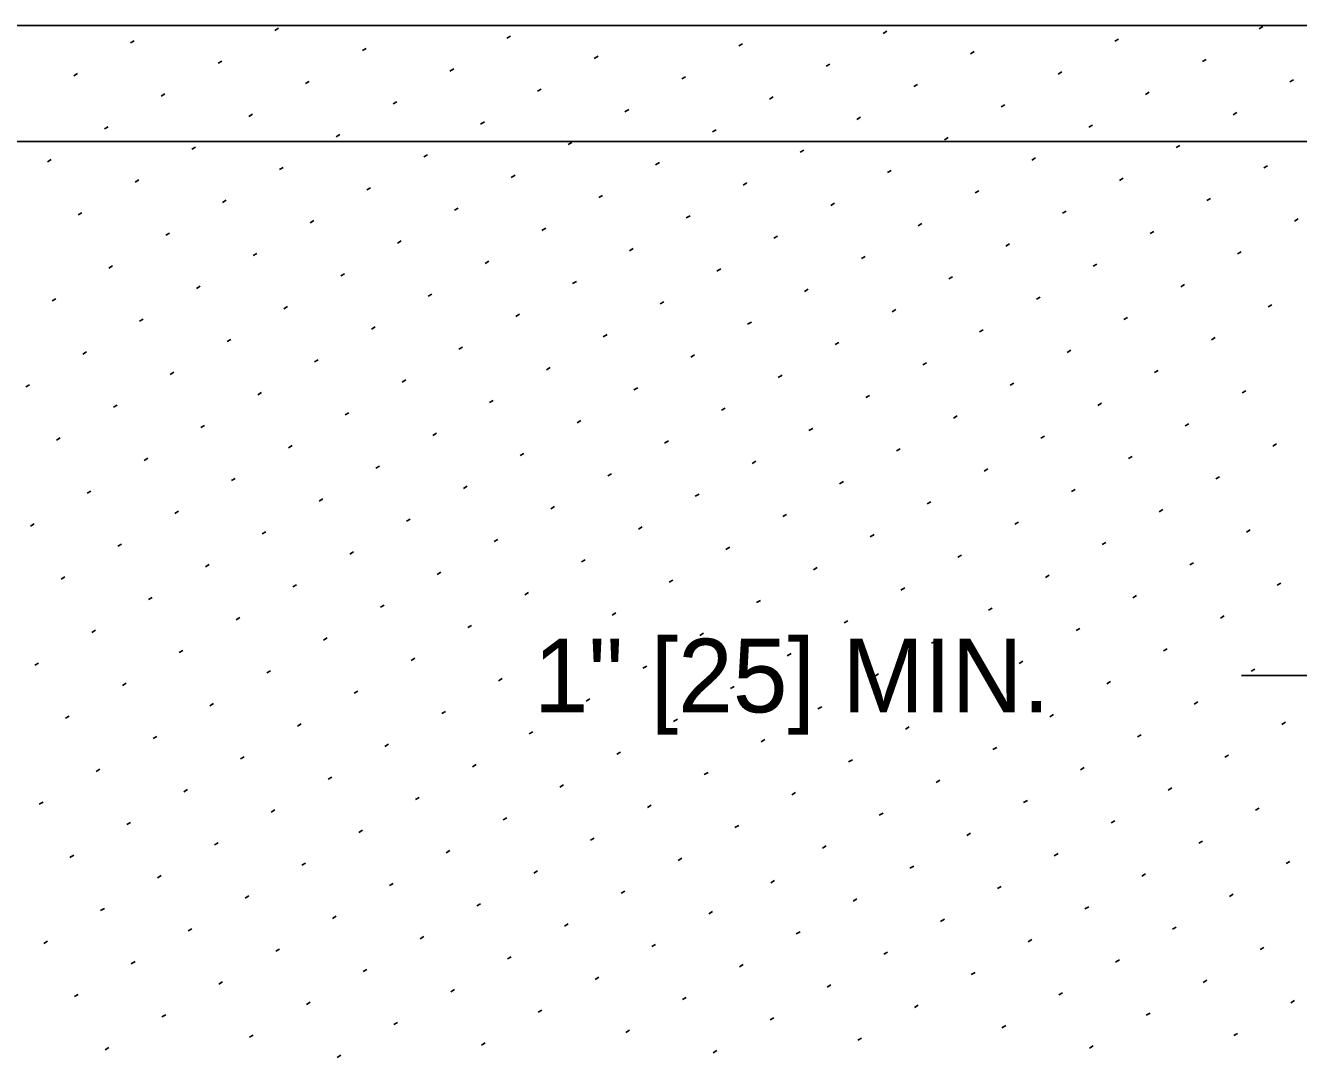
# Model space of a CAD drawing. Extents: x 49991.4 to 50021, y 49987.6 to 50011.4.
# Drawn here: x 50004.842 to 50005.88, y 49994.036 to 49994.877 of the extents above; entities that cross this region are included whole.
import ezdxf

# ---------------------------------------------------------------- set-up
doc = ezdxf.new("R2010")
doc.units = 0
for name, color, linetype in [('Level 1', 7, 'Continuous'), ('Level 2', 7, 'Continuous'), ('Level 3', 7, 'Continuous')]:
    doc.layers.add(name, color=color, linetype=linetype)

msp = doc.modelspace()

# ---------------------------------------------------------------- linework, layer by layer
at = {"layer": 'Level 1'}
for p, q in [((50004.5362, 49994.8772), (50008.0315, 49994.8772)), ((50008.0315, 49994.7828), (50001.9803, 49994.7828))]:
    msp.add_line(p, q, dxfattribs=at)
at = {"layer": 'Level 3'}
for p, q in [((50005.0452, 49994.8732), (50005.0482, 49994.875)), ((50005.3519, 49994.8771), (50005.3521, 49994.8772)), ((50005.5409, 49994.8707), (50005.5439, 49994.8725)), ((50005.8476, 49994.8746), (50005.8506, 49994.8763)), ((50004.9275, 49994.863), (50004.9305, 49994.8647)), ((50005.2342, 49994.8669), (50005.2372, 49994.8686)), ((50005.4232, 49994.8605), (50005.4262, 49994.8623)), ((50005.7299, 49994.8644), (50005.7329, 49994.8661)), ((50005.1165, 49994.8567), (50005.1195, 49994.8584)), ((50005.3055, 49994.8503), (50005.3086, 49994.8521)), ((50005.6122, 49994.8542), (50005.6152, 49994.8559)), ((50005.8012, 49994.8478), (50005.8043, 49994.8496)), ((50004.8812, 49994.8362), (50004.8842, 49994.838)), ((50004.9988, 49994.8464), (50005.0019, 49994.8482)), ((50005.1878, 49994.8401), (50005.1909, 49994.8419)), ((50005.4945, 49994.844), (50005.4976, 49994.8457)), ((50005.6836, 49994.8376), (50005.6866, 49994.8394)), ((50005.0702, 49994.8299), (50005.0732, 49994.8317)), ((50005.3769, 49994.8338), (50005.3799, 49994.8355)), ((50005.5659, 49994.8274), (50005.5689, 49994.8292)), ((50005.8726, 49994.8313), (50005.8756, 49994.833)), ((50004.9525, 49994.8197), (50004.9555, 49994.8214)), ((50005.2592, 49994.8236), (50005.2622, 49994.8253)), ((50005.4482, 49994.8172), (50005.4512, 49994.819)), ((50005.7549, 49994.8211), (50005.7579, 49994.8228)), ((50005.1415, 49994.8134), (50005.1445, 49994.8151)), ((50005.3305, 49994.807), (50005.3336, 49994.8088)), ((50005.6372, 49994.8109), (50005.6402, 49994.8126)), ((50005.0238, 49994.8031), (50005.0269, 49994.8049)), ((50005.2128, 49994.7968), (50005.2159, 49994.7986)), ((50005.5195, 49994.8007), (50005.5226, 49994.8024)), ((50005.8262, 49994.8045), (50005.8293, 49994.8063)), ((50004.9062, 49994.7929), (50004.9092, 49994.7947)), ((50005.0952, 49994.7866), (50005.0982, 49994.7883)), ((50005.4019, 49994.7905), (50005.4049, 49994.7922)), ((50005.7086, 49994.7943), (50005.7116, 49994.7961)), ((50004.9775, 49994.7764), (50004.9805, 49994.7781)), ((50005.2842, 49994.7803), (50005.2872, 49994.782)), ((50005.4732, 49994.7739), (50005.4762, 49994.7757)), ((50005.5909, 49994.7841), (50005.5939, 49994.7859)), ((50005.7799, 49994.7778), (50005.7829, 49994.7795)), ((50004.8598, 49994.7662), (50004.8628, 49994.7679)), ((50005.1665, 49994.7701), (50005.1695, 49994.7718)), ((50005.3555, 49994.7637), (50005.3586, 49994.7655)), ((50005.6622, 49994.7676), (50005.6652, 49994.7693)), ((50005.0488, 49994.7598), (50005.0519, 49994.7616)), ((50005.2378, 49994.7535), (50005.2409, 49994.7553)), ((50005.5445, 49994.7574), (50005.5476, 49994.7591)), ((50005.8512, 49994.7612), (50005.8543, 49994.763)), ((50004.9312, 49994.7496), (50004.9342, 49994.7514)), ((50005.1202, 49994.7433), (50005.1232, 49994.745)), ((50005.4269, 49994.7472), (50005.4299, 49994.7489)), ((50005.7336, 49994.751), (50005.7366, 49994.7528)), ((50005.0025, 49994.7331), (50005.0055, 49994.7348)), ((50005.3092, 49994.737), (50005.3122, 49994.7387)), ((50005.6159, 49994.7408), (50005.6189, 49994.7426)), ((50005.8049, 49994.7345), (50005.8079, 49994.7362)), ((50004.8848, 49994.7229), (50004.8878, 49994.7246)), ((50005.1915, 49994.7268), (50005.1945, 49994.7285)), ((50005.4982, 49994.7306), (50005.5012, 49994.7324)), ((50005.6872, 49994.7243), (50005.6902, 49994.726)), ((50005.0738, 49994.7165), (50005.0769, 49994.7183)), ((50005.3805, 49994.7204), (50005.3836, 49994.7222)), ((50005.5695, 49994.7141), (50005.5726, 49994.7158)), ((50005.8762, 49994.7179), (50005.8793, 49994.7197)), ((50004.9562, 49994.7063), (50004.9592, 49994.7081)), ((50005.2628, 49994.7102), (50005.2659, 49994.712)), ((50005.4519, 49994.7039), (50005.4549, 49994.7056)), ((50005.7586, 49994.7077), (50005.7616, 49994.7095)), ((50005.1452, 49994.7), (50005.1482, 49994.7017)), ((50005.3342, 49994.6937), (50005.3372, 49994.6954)), ((50005.6409, 49994.6975), (50005.6439, 49994.6993)), ((50005.8299, 49994.6912), (50005.8329, 49994.6929)), ((50005.0275, 49994.6898), (50005.0305, 49994.6915)), ((50005.2165, 49994.6834), (50005.2195, 49994.6852)), ((50005.5232, 49994.6873), (50005.5262, 49994.6891)), ((50005.7122, 49994.681), (50005.7152, 49994.6827)), ((50004.9098, 49994.6796), (50004.9128, 49994.6813)), ((50005.0988, 49994.6732), (50005.1019, 49994.675)), ((50005.4055, 49994.6771), (50005.4086, 49994.6789)), ((50005.5945, 49994.6708), (50005.5976, 49994.6725)), ((50004.9812, 49994.663), (50004.9842, 49994.6648)), ((50005.2878, 49994.6669), (50005.2909, 49994.6687)), ((50005.4769, 49994.6606), (50005.4799, 49994.6623)), ((50005.7836, 49994.6644), (50005.7866, 49994.6662)), ((50004.8635, 49994.6528), (50004.8665, 49994.6546)), ((50005.1702, 49994.6567), (50005.1732, 49994.6584)), ((50005.3592, 49994.6504), (50005.3622, 49994.6521)), ((50005.6659, 49994.6542), (50005.6689, 49994.656)), ((50005.0525, 49994.6465), (50005.0555, 49994.6482)), ((50005.2415, 49994.6401), (50005.2445, 49994.6419)), ((50005.5482, 49994.644), (50005.5512, 49994.6458)), ((50005.8549, 49994.6479), (50005.8579, 49994.6496)), ((50004.9348, 49994.6363), (50004.9378, 49994.638)), ((50005.1238, 49994.6299), (50005.1269, 49994.6317)), ((50005.4305, 49994.6338), (50005.4336, 49994.6356)), ((50005.7372, 49994.6377), (50005.7402, 49994.6394)), ((50005.0062, 49994.6197), (50005.0092, 49994.6215)), ((50005.3128, 49994.6236), (50005.3159, 49994.6254)), ((50005.6195, 49994.6275), (50005.6226, 49994.6292)), ((50005.8086, 49994.6211), (50005.8116, 49994.6229)), ((50004.8885, 49994.6095), (50004.8915, 49994.6113)), ((50005.1952, 49994.6134), (50005.1982, 49994.6151)), ((50005.5019, 49994.6173), (50005.5049, 49994.619)), ((50005.6909, 49994.6109), (50005.6939, 49994.6127)), ((50005.0775, 49994.6032), (50005.0805, 49994.6049)), ((50005.3842, 49994.6071), (50005.3872, 49994.6088)), ((50005.5732, 49994.6007), (50005.5762, 49994.6025)), ((50004.9598, 49994.593), (50004.9628, 49994.5947)), ((50005.2665, 49994.5968), (50005.2695, 49994.5986)), ((50005.4555, 49994.5905), (50005.4586, 49994.5923)), ((50005.7622, 49994.5944), (50005.7652, 49994.5961)), ((50004.8421, 49994.5828), (50004.8452, 49994.5845)), ((50005.1488, 49994.5866), (50005.1519, 49994.5884)), ((50005.3378, 49994.5803), (50005.3409, 49994.582)), ((50005.6445, 49994.5842), (50005.6476, 49994.5859)), ((50005.8336, 49994.5778), (50005.8366, 49994.5796)), ((50005.0312, 49994.5764), (50005.0342, 49994.5782)), ((50005.2202, 49994.5701), (50005.2232, 49994.5718)), ((50005.5269, 49994.574), (50005.5299, 49994.5757)), ((50005.7159, 49994.5676), (50005.7189, 49994.5694)), ((50004.9135, 49994.5662), (50004.9165, 49994.568)), ((50005.1025, 49994.5599), (50005.1055, 49994.5616)), ((50005.4092, 49994.5638), (50005.4122, 49994.5655)), ((50005.5982, 49994.5574), (50005.6012, 49994.5592)), ((50004.9848, 49994.5497), (50004.9878, 49994.5514)), ((50005.2915, 49994.5535), (50005.2945, 49994.5553)), ((50005.4805, 49994.5472), (50005.4836, 49994.549)), ((50005.7872, 49994.5511), (50005.7902, 49994.5528)), ((50004.8671, 49994.5395), (50004.8702, 49994.5412)), ((50005.1738, 49994.5433), (50005.1769, 49994.5451)), ((50005.3628, 49994.537), (50005.3659, 49994.5387)), ((50005.6695, 49994.5409), (50005.6726, 49994.5426)), ((50005.0562, 49994.5331), (50005.0592, 49994.5349)), ((50005.2452, 49994.5268), (50005.2482, 49994.5285)), ((50005.5519, 49994.5307), (50005.5549, 49994.5324)), ((50005.8586, 49994.5345), (50005.8616, 49994.5363)), ((50004.9385, 49994.5229), (50004.9415, 49994.5247)), ((50005.1275, 49994.5166), (50005.1305, 49994.5183)), ((50005.4342, 49994.5204), (50005.4372, 49994.5222)), ((50005.7409, 49994.5243), (50005.7439, 49994.5261)), ((50005.0098, 49994.5064), (50005.0128, 49994.5081)), ((50005.3165, 49994.5102), (50005.3195, 49994.512)), ((50005.6232, 49994.5141), (50005.6262, 49994.5159)), ((50005.8122, 49994.5078), (50005.8152, 49994.5095)), ((50004.8921, 49994.4962), (50004.8952, 49994.4979)), ((50005.1988, 49994.5), (50005.2019, 49994.5018)), ((50005.3878, 49994.4937), (50005.3909, 49994.4954)), ((50005.5055, 49994.5039), (50005.5086, 49994.5057)), ((50005.6945, 49994.4976), (50005.6976, 49994.4993)), ((50005.0812, 49994.4898), (50005.0842, 49994.4916)), ((50005.2702, 49994.4835), (50005.2732, 49994.4852)), ((50005.5769, 49994.4874), (50005.5799, 49994.4891)), ((50004.9635, 49994.4796), (50004.9665, 49994.4814)), ((50005.1525, 49994.4733), (50005.1555, 49994.475)), ((50005.4592, 49994.4771), (50005.4622, 49994.4789)), ((50005.7659, 49994.481), (50005.7689, 49994.4828)), ((50004.8458, 49994.4694), (50004.8488, 49994.4712)), ((50005.0348, 49994.4631), (50005.0378, 49994.4648)), ((50005.3415, 49994.4669), (50005.3445, 49994.4687)), ((50005.6482, 49994.4708), (50005.6512, 49994.4726)), ((50005.8372, 49994.4645), (50005.8402, 49994.4662)), ((50004.9171, 49994.4529), (50004.9202, 49994.4546)), ((50005.2238, 49994.4567), (50005.2269, 49994.4585)), ((50005.5305, 49994.4606), (50005.5336, 49994.4624)), ((50005.7195, 49994.4543), (50005.7226, 49994.456)), ((50005.1062, 49994.4465), (50005.1092, 49994.4483)), ((50005.4128, 49994.4504), (50005.4159, 49994.4521)), ((50005.6019, 49994.4441), (50005.6049, 49994.4458)), ((50004.9885, 49994.4363), (50004.9915, 49994.4381)), ((50005.2952, 49994.4402), (50005.2982, 49994.4419)), ((50005.4842, 49994.4338), (50005.4872, 49994.4356)), ((50005.7909, 49994.4377), (50005.7939, 49994.4395)), ((50004.8708, 49994.4261), (50004.8738, 49994.4279)), ((50005.1775, 49994.43), (50005.1805, 49994.4317)), ((50005.3665, 49994.4236), (50005.3695, 49994.4254)), ((50005.6732, 49994.4275), (50005.6762, 49994.4293)), ((50005.8622, 49994.4212), (50005.8652, 49994.4229)), ((50005.0598, 49994.4198), (50005.0628, 49994.4215)), ((50005.2488, 49994.4134), (50005.2519, 49994.4152)), ((50005.5555, 49994.4173), (50005.5586, 49994.419)), ((50005.7445, 49994.411), (50005.7476, 49994.4127)), ((50004.9421, 49994.4096), (50004.9452, 49994.4113)), ((50005.1312, 49994.4032), (50005.1342, 49994.405)), ((50005.4378, 49994.4071), (50005.4409, 49994.4088)), ((50005.6269, 49994.4008), (50005.6299, 49994.4025)), ((50005.0135, 49994.393), (50005.0165, 49994.3948)), ((50005.3202, 49994.3969), (50005.3232, 49994.3986)), ((50005.5092, 49994.3905), (50005.5122, 49994.3923)), ((50005.8159, 49994.3944), (50005.8189, 49994.3962)), ((50004.8958, 49994.3828), (50004.8988, 49994.3846)), ((50005.2025, 49994.3867), (50005.2055, 49994.3884)), ((50005.3915, 49994.3803), (50005.3945, 49994.3821)), ((50005.6982, 49994.3842), (50005.7012, 49994.386)), ((50005.0848, 49994.3765), (50005.0878, 49994.3782)), ((50005.2738, 49994.3701), (50005.2769, 49994.3719)), ((50005.5805, 49994.374), (50005.5836, 49994.3757)), ((50004.9671, 49994.3663), (50004.9702, 49994.368)), ((50005.1562, 49994.3599), (50005.1592, 49994.3617)), ((50005.4628, 49994.3638), (50005.4659, 49994.3655)), ((50005.7695, 49994.3677), (50005.7726, 49994.3694)), ((50004.8495, 49994.3561), (50004.8525, 49994.3578)), ((50005.0385, 49994.3497), (50005.0415, 49994.3515)), ((50005.3452, 49994.3536), (50005.3482, 49994.3553)), ((50005.6519, 49994.3575), (50005.6549, 49994.3592)), ((50005.8409, 49994.3511), (50005.8439, 49994.3529)), ((50004.9208, 49994.3395), (50004.9238, 49994.3413)), ((50005.2275, 49994.3434), (50005.2305, 49994.3451)), ((50005.5342, 49994.3472), (50005.5372, 49994.349)), ((50005.7232, 49994.3409), (50005.7262, 49994.3427)), ((50006.0016, 49994.3476), (50005.833, 49994.3476)), ((50005.1098, 49994.3332), (50005.1128, 49994.3349)), ((50005.4165, 49994.337), (50005.4195, 49994.3388)), ((50005.6055, 49994.3307), (50005.6086, 49994.3324)), ((50004.9921, 49994.323), (50004.9952, 49994.3247)), ((50005.2988, 49994.3268), (50005.3019, 49994.3286)), ((50005.4878, 49994.3205), (50005.4909, 49994.3222)), ((50005.7945, 49994.3244), (50005.7976, 49994.3261)), ((50004.8745, 49994.3128), (50004.8775, 49994.3145)), ((50005.1812, 49994.3166), (50005.1842, 49994.3184)), ((50005.3702, 49994.3103), (50005.3732, 49994.312)), ((50005.6769, 49994.3141), (50005.6799, 49994.3159)), ((50005.8659, 49994.3078), (50005.8689, 49994.3096)), ((50005.0635, 49994.3064), (50005.0665, 49994.3082)), ((50005.2525, 49994.3001), (50005.2555, 49994.3018)), ((50005.5592, 49994.3039), (50005.5622, 49994.3057)), ((50005.7482, 49994.2976), (50005.7512, 49994.2994)), ((50004.9458, 49994.2962), (50004.9488, 49994.298)), ((50005.1348, 49994.2899), (50005.1378, 49994.2916)), ((50005.4415, 49994.2937), (50005.4445, 49994.2955)), ((50005.6305, 49994.2874), (50005.6336, 49994.2891)), ((50005.0171, 49994.2797), (50005.0202, 49994.2814)), ((50005.3238, 49994.2835), (50005.3269, 49994.2853)), ((50005.5128, 49994.2772), (50005.5159, 49994.2789)), ((50005.8195, 49994.2811), (50005.8226, 49994.2828)), ((50004.8995, 49994.2695), (50004.9025, 49994.2712)), ((50005.2062, 49994.2733), (50005.2092, 49994.2751)), ((50005.3952, 49994.267), (50005.3982, 49994.2687)), ((50005.7019, 49994.2708), (50005.7049, 49994.2726)), ((50005.0885, 49994.2631), (50005.0915, 49994.2649)), ((50005.2775, 49994.2568), (50005.2805, 49994.2585)), ((50005.5842, 49994.2606), (50005.5872, 49994.2624)), ((50004.9708, 49994.2529), (50004.9738, 49994.2547)), ((50005.1598, 49994.2466), (50005.1628, 49994.2483)), ((50005.4665, 49994.2504), (50005.4695, 49994.2522)), ((50005.7732, 49994.2543), (50005.7762, 49994.2561)), ((50004.8531, 49994.2427), (50004.8562, 49994.2445)), ((50005.0421, 49994.2364), (50005.0452, 49994.2381)), ((50005.3488, 49994.2402), (50005.3519, 49994.242)), ((50005.6555, 49994.2441), (50005.6586, 49994.2458)), ((50005.8445, 49994.2378), (50005.8476, 49994.2395)), ((50004.9245, 49994.2262), (50004.9275, 49994.2279)), ((50005.2312, 49994.23), (50005.2342, 49994.2318)), ((50005.5378, 49994.2339), (50005.5409, 49994.2356)), ((50005.7269, 49994.2275), (50005.7299, 49994.2293)), ((50005.1135, 49994.2198), (50005.1165, 49994.2216)), ((50005.3025, 49994.2135), (50005.3055, 49994.2152)), ((50005.4202, 49994.2237), (50005.4232, 49994.2254)), ((50005.6092, 49994.2173), (50005.6122, 49994.2191)), ((50004.9958, 49994.2096), (50004.9988, 49994.2114)), ((50005.1848, 49994.2033), (50005.1878, 49994.205)), ((50005.4915, 49994.2071), (50005.4945, 49994.2089)), ((50005.7982, 49994.211), (50005.8012, 49994.2127)), ((50004.8781, 49994.1994), (50004.8812, 49994.2012)), ((50005.0671, 49994.1931), (50005.0702, 49994.1948)), ((50005.3738, 49994.1969), (50005.3769, 49994.1987)), ((50005.6805, 49994.2008), (50005.6836, 49994.2025)), ((50005.8695, 49994.1945), (50005.8726, 49994.1962)), ((50004.9495, 49994.1829), (50004.9525, 49994.1846)), ((50005.2562, 49994.1867), (50005.2592, 49994.1885)), ((50005.5628, 49994.1906), (50005.5659, 49994.1923)), ((50005.7519, 49994.1842), (50005.7549, 49994.186)), ((50005.1385, 49994.1765), (50005.1415, 49994.1783)), ((50005.4493, 49994.1788), (50005.4524, 49994.1805)), ((50005.6342, 49994.174), (50005.6372, 49994.1758)), ((50005.0208, 49994.1663), (50005.0238, 49994.1681)), ((50005.3275, 49994.1702), (50005.3305, 49994.1719)), ((50005.5165, 49994.1638), (50005.5195, 49994.1656)), ((50005.8232, 49994.1677), (50005.8262, 49994.1694)), ((50004.9031, 49994.1561), (50004.9062, 49994.1579)), ((50005.2098, 49994.16), (50005.2128, 49994.1617)), ((50005.3988, 49994.1536), (50005.4019, 49994.1554)), ((50005.7055, 49994.1575), (50005.7086, 49994.1592)), ((50005.0921, 49994.1498), (50005.0952, 49994.1515)), ((50005.2812, 49994.1434), (50005.2842, 49994.1452)), ((50005.5878, 49994.1473), (50005.5909, 49994.149)), ((50005.7769, 49994.1409), (50005.7799, 49994.1427)), ((50004.9745, 49994.1396), (50004.9775, 49994.1413)), ((50005.1635, 49994.1332), (50005.1665, 49994.135)), ((50005.4702, 49994.1371), (50005.4732, 49994.1388)), ((50005.6592, 49994.1307), (50005.6622, 49994.1325)), ((50004.8568, 49994.1294), (50004.8598, 49994.1311)), ((50005.0458, 49994.123), (50005.0488, 49994.1248)), ((50005.3525, 49994.1269), (50005.3555, 49994.1286)), ((50005.5415, 49994.1205), (50005.5445, 49994.1223)), ((50005.8482, 49994.1244), (50005.8512, 49994.1261)), ((50004.9281, 49994.1128), (50004.9312, 49994.1146)), ((50005.2348, 49994.1167), (50005.2378, 49994.1184)), ((50005.4238, 49994.1103), (50005.4269, 49994.1121)), ((50005.7305, 49994.1142), (50005.7336, 49994.1159)), ((50005.1171, 49994.1065), (50005.1202, 49994.1082)), ((50005.3062, 49994.1001), (50005.3092, 49994.1019)), ((50005.6128, 49994.104), (50005.6159, 49994.1057)), ((50004.9995, 49994.0963), (50005.0025, 49994.098)), ((50005.1885, 49994.0899), (50005.1915, 49994.0917)), ((50005.4952, 49994.0938), (50005.4982, 49994.0955)), ((50005.8019, 49994.0976), (50005.8049, 49994.0994)), ((50004.8818, 49994.0861), (50004.8848, 49994.0878)), ((50005.0708, 49994.0797), (50005.0738, 49994.0815)), ((50005.3775, 49994.0836), (50005.3805, 49994.0853)), ((50005.6842, 49994.0874), (50005.6872, 49994.0892)), ((50005.8732, 49994.0811), (50005.8762, 49994.0828)), ((50004.9531, 49994.0695), (50004.9562, 49994.0713)), ((50005.2598, 49994.0734), (50005.2628, 49994.0751)), ((50005.5665, 49994.0772), (50005.5695, 49994.079)), ((50005.7555, 49994.0709), (50005.7586, 49994.0726)), ((50005.1421, 49994.0632), (50005.1452, 49994.0649)), ((50005.4488, 49994.067), (50005.4519, 49994.0688)), ((50005.6378, 49994.0607), (50005.6409, 49994.0624)), ((50005.0245, 49994.053), (50005.0275, 49994.0547)), ((50005.3312, 49994.0568), (50005.3342, 49994.0586)), ((50005.5202, 49994.0505), (50005.5232, 49994.0522)), ((50005.8269, 49994.0543), (50005.8299, 49994.0561)), ((50004.9068, 49994.0428), (50004.9098, 49994.0445)), ((50005.2135, 49994.0466), (50005.2165, 49994.0484)), ((50005.4025, 49994.0403), (50005.4055, 49994.042)), ((50005.7092, 49994.0441), (50005.7122, 49994.0459)), ((50005.0958, 49994.0364), (50005.0988, 49994.0382))]:
    msp.add_line(p, q, dxfattribs=at)

# ---------------------------------------------------------------- texts
at = {"layer": 'Level 2'}
msp.add_text('1" [25] MIN.', height=0.06, dxfattribs=at).set_placement((50005.2561, 49994.3176))

doc.saveas('drawing.dxf')
